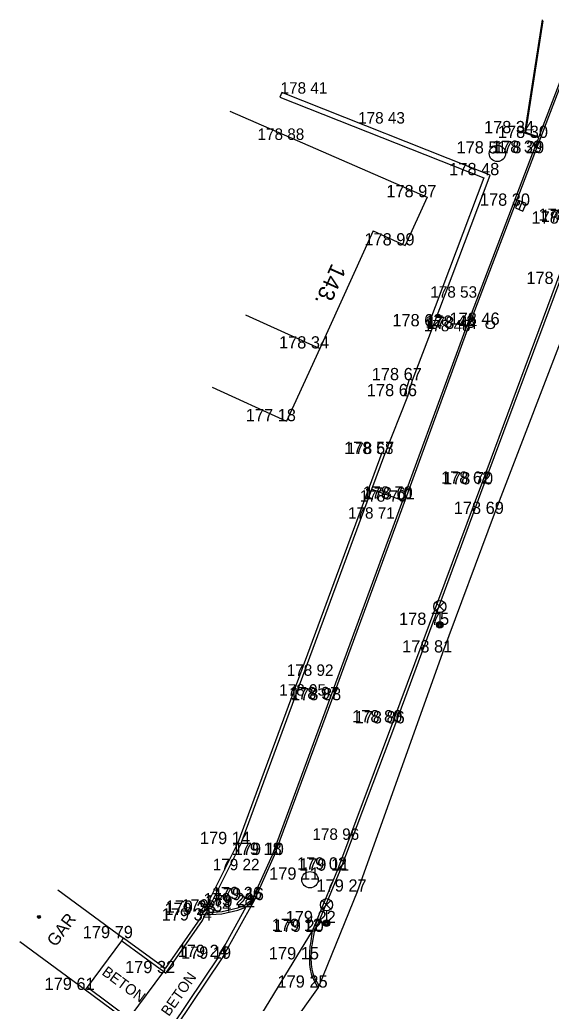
# Model space of a CAD drawing. Extents: x -537755 to -537431, y -1180722 to -1180510.
# Drawn here: x -537579.5 to -537546.9, y -1180583.9 to -1180523.7 of the extents above; entities that cross this region are included whole.
import ezdxf

# ---------------------------------------------------------------- set-up
doc = ezdxf.new("R2010")
doc.units = 0
for name, color, linetype in [('Vrstva 1', 7, 'Continuous'), ('Vrstva 10', 7, 'Continuous'), ('Vrstva 11', 7, 'Continuous'), ('Vrstva 27', 7, 'Continuous'), ('Vrstva 28', 7, 'Continuous'), ('Vrstva 3', 7, 'Continuous'), ('Vrstva 33', 7, 'Continuous'), ('Vrstva 39', 7, 'Continuous'), ('Vrstva 40', 7, 'Continuous'), ('Vrstva 41', 7, 'Continuous'), ('Vrstva 47', 7, 'Continuous'), ('Vrstva 5', 7, 'Continuous'), ('Vrstva 7', 7, 'Continuous'), ('Vrstva 8', 7, 'Continuous')]:
    doc.layers.add(name, color=color, linetype=linetype)

msp = doc.modelspace()

# ---------------------------------------------------------------- linework, layer by layer
at = {"layer": 'Vrstva 1'}
for p, q in [((-537561.17, -1180528.23), (-537561.17, -1180528.23)), ((-537556.42, -1180530.06), (-537556.42, -1180530.06)), ((-537562.58, -1180531.06), (-537562.58, -1180531.06)), ((-537548.55, -1180530.65), (-537548.55, -1180530.65)), ((-537547.7, -1180530.94), (-537547.7, -1180530.94)), ((-537550.23, -1180531.89), (-537550.23, -1180531.89)), ((-537548.06, -1180531.85), (-537548.06, -1180531.85)), ((-537547.93, -1180531.88), (-537547.93, -1180531.88)), ((-537550.68, -1180533.22), (-537550.68, -1180533.22)), ((-537554.53, -1180534.57), (-537554.53, -1180534.57)), ((-537548.8, -1180535.09), (-537548.8, -1180535.09)), ((-537555.87, -1180537.52), (-537555.87, -1180537.52)), ((-537552, -1180540.72), (-537552, -1180540.72)), ((-537554.16, -1180542.47), (-537554.16, -1180542.47)), ((-537552.14, -1180542.56), (-537552.14, -1180542.56)), ((-537552.04, -1180542.63), (-537552.04, -1180542.63)), ((-537550.66, -1180542.38), (-537550.66, -1180542.38)), ((-537552.4, -1180542.78), (-537552.4, -1180542.78)), ((-537561.1, -1180543.83), (-537561.1, -1180543.83)), ((-537555.42, -1180545.77), (-537555.42, -1180545.77)), ((-537555.72, -1180546.75), (-537555.72, -1180546.75)), ((-537563.13, -1180548.28), (-537563.13, -1180548.28)), ((-537557.12, -1180550.29), (-537557.12, -1180550.29)), ((-537557.11, -1180550.29), (-537557.11, -1180550.29)), ((-537551.18, -1180552.11), (-537551.18, -1180552.11)), ((-537551.06, -1180552.15), (-537551.06, -1180552.15)), ((-537556.32, -1180553.21), (-537556.32, -1180553.21)), ((-537555.98, -1180553.02), (-537555.98, -1180553.02)), ((-537555.86, -1180553.07), (-537555.86, -1180553.07)), ((-537550.4, -1180553.96), (-537550.4, -1180553.96)), ((-537557.04, -1180554.25), (-537557.04, -1180554.25)), ((-537553.75, -1180560.75), (-537553.75, -1180560.75)), ((-537553.74, -1180560.75), (-537553.74, -1180560.75)), ((-537553.56, -1180562.44), (-537553.56, -1180562.44)), ((-537560.79, -1180563.87), (-537560.79, -1180563.87)), ((-537561.25, -1180565.08), (-537561.25, -1180565.08)), ((-537560.48, -1180565.3), (-537560.48, -1180565.3)), ((-537560.36, -1180565.36), (-537560.36, -1180565.36)), ((-537556.62, -1180566.72), (-537556.62, -1180566.72)), ((-537556.47, -1180566.78), (-537556.47, -1180566.78)), ((-537559.22, -1180573.91), (-537559.22, -1180573.91)), ((-537565.94, -1180574.17), (-537565.94, -1180574.17)), ((-537564, -1180574.83), (-537564, -1180574.83)), ((-537563.87, -1180574.84), (-537563.87, -1180574.84)), ((-537565.32, -1180575.77), (-537565.32, -1180575.77)), ((-537560, -1180575.73), (-537560, -1180575.73)), ((-537561.7, -1180576.35), (-537561.7, -1180576.35)), ((-537559.87, -1180575.8), (-537559.87, -1180575.8)), ((-537565.21, -1180577.54), (-537565.21, -1180577.54)), ((-537558.8, -1180577.08), (-537558.8, -1180577.08)), ((-537565.72, -1180577.92), (-537565.72, -1180577.92)), ((-537565.62, -1180578.04), (-537565.62, -1180578.04)), ((-537565.09, -1180577.6), (-537565.09, -1180577.6)), ((-537568.11, -1180578.51), (-537568.11, -1180578.51)), ((-537568.04, -1180578.37), (-537568.04, -1180578.37)), ((-537567.08, -1180578.3), (-537567.08, -1180578.3)), ((-537568.28, -1180578.85), (-537568.28, -1180578.85)), ((-537560.69, -1180579.01), (-537560.69, -1180579.01)), ((-537560.68, -1180579.01), (-537560.68, -1180579.01)), ((-537573.11, -1180579.93), (-537573.11, -1180579.93)), ((-537561.54, -1180579.49), (-537561.54, -1180579.49)), ((-537561.43, -1180579.55), (-537561.43, -1180579.55)), ((-537567.3, -1180581.08), (-537567.3, -1180581.08)), ((-537567.1, -1180581.19), (-537567.1, -1180581.19)), ((-537561.72, -1180581.23), (-537561.72, -1180581.23)), ((-537570.52, -1180582.07), (-537570.52, -1180582.07)), ((-537561.19, -1180582.96), (-537561.19, -1180582.96)), ((-537575.45, -1180583.1), (-537575.45, -1180583.1))]:
    msp.add_line(p, q, dxfattribs=at)
at = {"layer": 'Vrstva 10'}
for p, q in [((-537547.93, -1180531.88), (-537545.86, -1180526.42)), ((-537552.04, -1180542.63), (-537547.93, -1180531.88)), ((-537551.18, -1180552.11), (-537545.21, -1180536.01)), ((-537555.86, -1180553.07), (-537552.04, -1180542.63)), ((-537556.62, -1180566.72), (-537551.18, -1180552.11)), ((-537560.36, -1180565.36), (-537555.86, -1180553.07)), ((-537563.87, -1180574.84), (-537560.36, -1180565.36)), ((-537560, -1180575.73), (-537556.62, -1180566.72)), ((-537561.54, -1180579.49), (-537560, -1180575.73)), ((-537565.39, -1180585.76), (-537561.54, -1180579.49)), ((-537570.52, -1180586.29), (-537567.1, -1180581.19))]:
    msp.add_line(p, q, dxfattribs=at)
for points in [[(-537567.1, -1180581.19), (-537565.09, -1180577.6), (-537563.87, -1180574.84)], [(-537561.19, -1180582.96), (-537561.313, -1180582.744), (-537561.436, -1180582.528), (-537561.475, -1180582.455), (-537561.509, -1180582.384), (-537561.537, -1180582.317), (-537561.562, -1180582.253), (-537561.602, -1180582.129), (-537561.631, -1180582.019), (-537561.653, -1180581.922), (-537561.669, -1180581.835), (-537561.691, -1180581.683), (-537561.703, -1180581.569), (-537561.715, -1180581.398), (-537561.72, -1180581.23), (-537561.72, -1180581.031), (-537561.716, -1180580.856), (-537561.707, -1180580.702), (-537561.696, -1180580.567), (-537561.682, -1180580.449), (-537561.668, -1180580.346), (-537561.654, -1180580.256), (-537561.54, -1180579.49)]]:
    msp.add_lwpolyline(points, dxfattribs=at)
at = {"layer": 'Vrstva 11'}
for p, q in [((-537548.55, -1180530.65), (-537547.47, -1180523.7)), ((-537548.495, -1180530.616), (-537547.429, -1180523.761)), ((-537547.684, -1180530.893), (-537548.495, -1180530.616)), ((-537547.7, -1180530.94), (-537548.55, -1180530.65)), ((-537548.06, -1180531.85), (-537547.7, -1180530.94)), ((-537552.14, -1180542.56), (-537548.06, -1180531.85)), ((-537545.07, -1180536.09), (-537551.06, -1180552.15)), ((-537555.98, -1180553.02), (-537552.14, -1180542.56)), ((-537551.06, -1180552.15), (-537556.47, -1180566.78)), ((-537557.908, -1180552.449), (-537556.026, -1180553.145)), ((-537564, -1180574.83), (-537560.48, -1180565.3)), ((-537556.47, -1180566.78), (-537559.87, -1180575.8)), ((-537565.21, -1180577.54), (-537564, -1180574.83)), ((-537559.87, -1180575.8), (-537561.43, -1180579.55)), ((-537567.3, -1180581.08), (-537570.72, -1180586.14))]:
    msp.add_line(p, q, dxfattribs=at)
for points in [[(-537547.7, -1180530.94), (-537547.684, -1180530.893), (-537545.92, -1180526.26)], [(-537560.48, -1180565.3), (-537556.026, -1180553.145)], [(-537556.026, -1180553.145), (-537555.98, -1180553.02)], [(-537565.72, -1180577.92), (-537565.21, -1180577.54), (-537565.09, -1180577.6), (-537565.62, -1180578.04), (-537567.3, -1180581.08)], [(-537568.11, -1180578.51), (-537567.106, -1180578.447), (-537566.124, -1180578.222), (-537565.62, -1180578.04)], [(-537568.04, -1180578.37), (-537567.08, -1180578.3), (-537566.108, -1180578.064), (-537565.72, -1180577.92)], [(-537561.142, -1180582.843), (-537561.348, -1180582.48), (-537561.386, -1180582.41), (-537561.418, -1180582.343), (-537561.444, -1180582.28), (-537561.468, -1180582.219), (-537561.506, -1180582.101), (-537561.534, -1180581.995), (-537561.555, -1180581.902), (-537561.57, -1180581.819), (-537561.592, -1180581.671), (-537561.603, -1180581.56), (-537561.615, -1180581.393), (-537561.62, -1180581.229), (-537561.62, -1180581.032), (-537561.616, -1180580.86), (-537561.607, -1180580.709), (-537561.596, -1180580.577), (-537561.583, -1180580.462), (-537561.569, -1180580.36), (-537561.555, -1180580.273), (-537561.526, -1180580.121), (-537561.43, -1180579.55)], [(-537570.72, -1180586.14), (-537572.71, -1180584.74), (-537570.658, -1180581.969)]]:
    msp.add_lwpolyline(points, dxfattribs=at)
at = {"layer": 'Vrstva 27'}
msp.add_line((-537548.896, -1180535.321), (-537548.704, -1180534.859), dxfattribs=at)
msp.add_lwpolyline([(-537548.665, -1180535.417), (-537548.473, -1180534.955), (-537548.935, -1180534.763), (-537549.127, -1180535.225)], close=True, dxfattribs=at)
for centre in [(-537550.23, -1180531.89), (-537561.7, -1180576.35)]:
    msp.add_circle(centre, 0.5, dxfattribs=at)
at = {"layer": 'Vrstva 28'}
msp.add_circle((-537550.66, -1180542.38), 0.25, dxfattribs=at)
at = {"layer": 'Vrstva 33'}
for p, q in [((-537554.014, -1180559.891), (-537553.486, -1180559.361)), ((-537554.014, -1180559.361), (-537553.486, -1180559.891)), ((-537553.75, -1180560), (-537553.75, -1180560.75)), ((-537560.954, -1180578.151), (-537560.426, -1180577.621)), ((-537560.954, -1180577.621), (-537560.426, -1180578.151)), ((-537560.69, -1180578.26), (-537560.69, -1180579.01))]:
    msp.add_line(p, q, dxfattribs=at)
for centre, radius in [((-537553.75, -1180559.626), 0.375), ((-537553.75, -1180560.751), 0.2), ((-537553.75, -1180560.751), 0.145), ((-537553.75, -1180560.751), 0.0876), ((-537560.69, -1180577.886), 0.375), ((-537560.69, -1180579.011), 0.2), ((-537560.69, -1180579.011), 0.145), ((-537560.69, -1180579.011), 0.0876)]:
    msp.add_circle(centre, radius, dxfattribs=at)
at = {"layer": 'Vrstva 39'}
for radius in [0.09, 0.0398]:
    msp.add_circle((-537578.298, -1180578.629), radius, dxfattribs=at)
at = {"layer": 'Vrstva 5'}
for p, q in [((-537566.613, -1180529.301), (-537554.53, -1180534.57)), ((-537554.53, -1180534.57), (-537555.87, -1180537.52)), ((-537557.829, -1180536.63), (-537561.1, -1180543.83)), ((-537557.829, -1180536.63), (-537555.87, -1180537.52)), ((-537565.652, -1180541.762), (-537561.1, -1180543.83)), ((-537561.1, -1180543.83), (-537563.13, -1180548.28)), ((-537567.679, -1180546.205), (-537563.13, -1180548.28)), ((-537577.133, -1180576.961), (-537573.11, -1180579.93)), ((-537573.228, -1180580.09), (-537573.11, -1180579.93)), ((-537579.473, -1180580.131), (-537575.45, -1180583.1)), ((-537575.331, -1180582.939), (-537573.228, -1180580.09)), ((-537575.45, -1180583.1), (-537575.331, -1180582.939))]:
    msp.add_line(p, q, dxfattribs=at)
at = {"layer": 'Vrstva 7'}
for p, q in [((-537563.54, -1180528.44), (-537551.065, -1180533.39)), ((-537551.065, -1180533.39), (-537554.441, -1180542.364)), ((-537550.4, -1180553.96), (-537543.58, -1180536.14)), ((-537555.911, -1180546.691), (-537555.611, -1180545.711)), ((-537557.298, -1180550.221), (-537566.124, -1180574.09)), ((-537565.94, -1180574.17), (-537557.908, -1180552.449)), ((-537553.56, -1180562.44), (-537550.4, -1180553.96)), ((-537558.8, -1180577.08), (-537553.56, -1180562.44)), ((-537566.124, -1180574.09), (-537568.452, -1180578.748)), ((-537575.45, -1180583.1), (-537572.779, -1180585.071))]:
    msp.add_line(p, q, dxfattribs=at)
for points in [[(-537563.429, -1180528.161), (-537563.54, -1180528.44)], [(-537550.68, -1180533.22), (-537563.429, -1180528.161)], [(-537554.16, -1180542.47), (-537550.68, -1180533.22)], [(-537554.441, -1180542.364), (-537554.16, -1180542.47)], [(-537555.911, -1180546.691), (-537555.72, -1180546.75), (-537555.42, -1180545.77), (-537555.611, -1180545.711)], [(-537557.908, -1180552.449), (-537557.11, -1180550.29), (-537557.298, -1180550.221)], [(-537568.28, -1180578.85), (-537568.11, -1180578.51), (-537568.04, -1180578.37), (-537565.94, -1180574.17)], [(-537561.142, -1180582.843), (-537558.8, -1180577.08)], [(-537568.452, -1180578.748), (-537570.567, -1180581.788), (-537573.11, -1180579.93)], [(-537573.228, -1180580.09), (-537570.658, -1180581.969), (-537570.52, -1180582.07), (-537568.28, -1180578.85)], [(-537575.331, -1180582.939), (-537572.66, -1180584.91), (-537572.779, -1180585.071)], [(-537561.19, -1180582.96), (-537561.142, -1180582.843)]]:
    msp.add_lwpolyline(points, dxfattribs=at)
at = {"layer": 'Vrstva 8'}
for p, q in [((-537555.42, -1180545.77), (-537554.16, -1180542.47)), ((-537557.11, -1180550.29), (-537555.72, -1180546.75)), ((-537561.19, -1180582.96), (-537563.17, -1180585.7))]:
    msp.add_line(p, q, dxfattribs=at)

# ---------------------------------------------------------------- texts
at = {"layer": 'Vrstva 3'}
for s, height, p in [('178 41 ', 0.7, (-537563.503, -1180528.23)), ('178 43 ', 0.7, (-537558.754, -1180530.06)), ('178 34 ', 0.75, (-537551.05, -1180530.65)), ('178 88 ', 0.7, (-537564.914, -1180531.06)), ('178 30 ', 0.75, (-537550.2, -1180530.94)), ('178 51 ', 0.75, (-537552.73, -1180531.89)), ('178 39 ', 0.75, (-537550.56, -1180531.85)), ('178 29 ', 0.75, (-537550.43, -1180531.88)), ('178 48 ', 0.75, (-537553.18, -1180533.22)), ('178 97 ', 0.75, (-537557.03, -1180534.57)), ('178 30 ', 0.75, (-537551.3, -1180535.09)), ('178 26 ', 0.75, (-537548.14, -1180536.18)), ('178 26 ', 0.75, (-537547.71, -1180536.01)), ('178 37 ', 0.75, (-537547.57, -1180536.09)), ('178 99 ', 0.75, (-537558.37, -1180537.52)), ('178 49 ', 0.75, (-537548.46, -1180539.88)), ('178 53 ', 0.7, (-537554.334, -1180540.72)), ('178 62 ', 0.75, (-537556.66, -1180542.47)), ('178 48 ', 0.75, (-537554.64, -1180542.56)), ('178 44 ', 0.75, (-537554.54, -1180542.63)), ('178 46 ', 0.75, (-537553.16, -1180542.38)), ('178 48 ', 0.7, (-537554.734, -1180542.78)), ('178 34 ', 0.75, (-537563.6, -1180543.83)), ('178 67 ', 0.75, (-537557.92, -1180545.77)), ('178 66 ', 0.75, (-537558.22, -1180546.75)), ('177 18 ', 0.75, (-537565.63, -1180548.28)), ('178 57 ', 0.75, (-537559.61, -1180550.29)), ('178 68 ', 0.7, (-537559.454, -1180550.29)), ('178 62 ', 0.75, (-537553.68, -1180552.11)), ('178 70 ', 0.75, (-537553.56, -1180552.15)), ('178 70 ', 0.75, (-537558.48, -1180553.02)), ('178 70 ', 0.7, (-537558.654, -1180553.21)), ('178 61 ', 0.75, (-537558.36, -1180553.07)), ('178 69 ', 0.75, (-537552.9, -1180553.96)), ('178 71 ', 0.7, (-537559.373, -1180554.25)), ('178 75 ', 0.75, (-537556.249, -1180560.75)), ('178 81 ', 0.75, (-537556.06, -1180562.44)), ('178 92 ', 0.7, (-537563.124, -1180563.87)), ('178 95 ', 0.7, (-537563.584, -1180565.08)), ('178 97 ', 0.75, (-537562.98, -1180565.3)), ('178 88 ', 0.75, (-537562.86, -1180565.36)), ('178 80 ', 0.75, (-537559.12, -1180566.72)), ('178 86 ', 0.75, (-537558.97, -1180566.78)), ('178 96 ', 0.7, (-537561.553, -1180573.91)), ('179 14 ', 0.75, (-537568.44, -1180574.17)), ('179 18 ', 0.75, (-537566.5, -1180574.83)), ('179 10 ', 0.75, (-537566.37, -1180574.84)), ('179 22 ', 0.7, (-537567.654, -1180575.77)), ('179 02 ', 0.75, (-537562.5, -1180575.73)), ('179 11 ', 0.75, (-537562.37, -1180575.8)), ('179 11 ', 0.75, (-537564.2, -1180576.35)), ('179 27 ', 0.75, (-537561.3, -1180577.08)), ('179 26 ', 0.75, (-537567.71, -1180577.54)), ('179 16 ', 0.75, (-537567.59, -1180577.6)), ('179 34 ', 0.75, (-537569.58, -1180578.3)), ('179 28 ', 0.75, (-537568.22, -1180577.92)), ('179 22 ', 0.75, (-537568.12, -1180578.04)), ('179 34 ', 0.75, (-537570.78, -1180578.85)), ('179 28 ', 0.75, (-537570.61, -1180578.51)), ('179 38 ', 0.75, (-537570.54, -1180578.37)), ('179 12 ', 0.75, (-537564.04, -1180579.49)), ('179 20 ', 0.75, (-537563.93, -1180579.55)), ('179 22 ', 0.75, (-537563.19, -1180579.01)), ('179 79 ', 0.75, (-537575.61, -1180579.93)), ('179 24 ', 0.75, (-537569.8, -1180581.08)), ('179 19 ', 0.75, (-537569.6, -1180581.19)), ('179 15 ', 0.75, (-537564.22, -1180581.23)), ('179 32 ', 0.75, (-537573.02, -1180582.07)), ('179 61 ', 0.75, (-537577.95, -1180583.1)), ('179 25 ', 0.75, (-537563.69, -1180582.96))]:
    msp.add_text(s, height=height, dxfattribs=at).set_placement(p)
at = {"layer": 'Vrstva 40'}
for rotation, p in [(323.57543, (-537574.491, -1180582.123)), (54.94557, (-537570.339, -1180584.759))]:
    msp.add_text('BETON', height=0.65, rotation=rotation, dxfattribs=at).set_placement(p)
at = {"layer": 'Vrstva 41'}
msp.add_text('GAR', height=0.75, rotation=53.56636, dxfattribs=at).set_placement((-537577.264, -1180580.505))
at = {"layer": 'Vrstva 47'}
msp.add_text('143.', height=1, rotation=245.56744, dxfattribs=at).set_placement((-537560.358, -1180538.57))

doc.saveas('drawing.dxf')
